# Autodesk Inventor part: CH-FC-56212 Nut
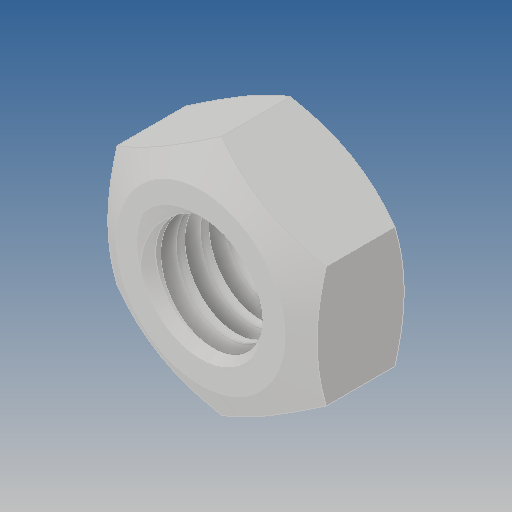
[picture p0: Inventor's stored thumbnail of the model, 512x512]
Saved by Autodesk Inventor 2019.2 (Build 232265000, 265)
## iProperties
Created: 2012-09
Part Number: CH-FC-56212 Nut
Material: Ogólny
Document SubType Name: Modeling
Designer: CADENGINEERING4
Density: 1 g/cm^3
Appearance: Domyślna
Author: CADENGINEERING4
Revision Number: ÈÎºÎ
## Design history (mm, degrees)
feature "¾µÏò1"
node "Bryła1"
